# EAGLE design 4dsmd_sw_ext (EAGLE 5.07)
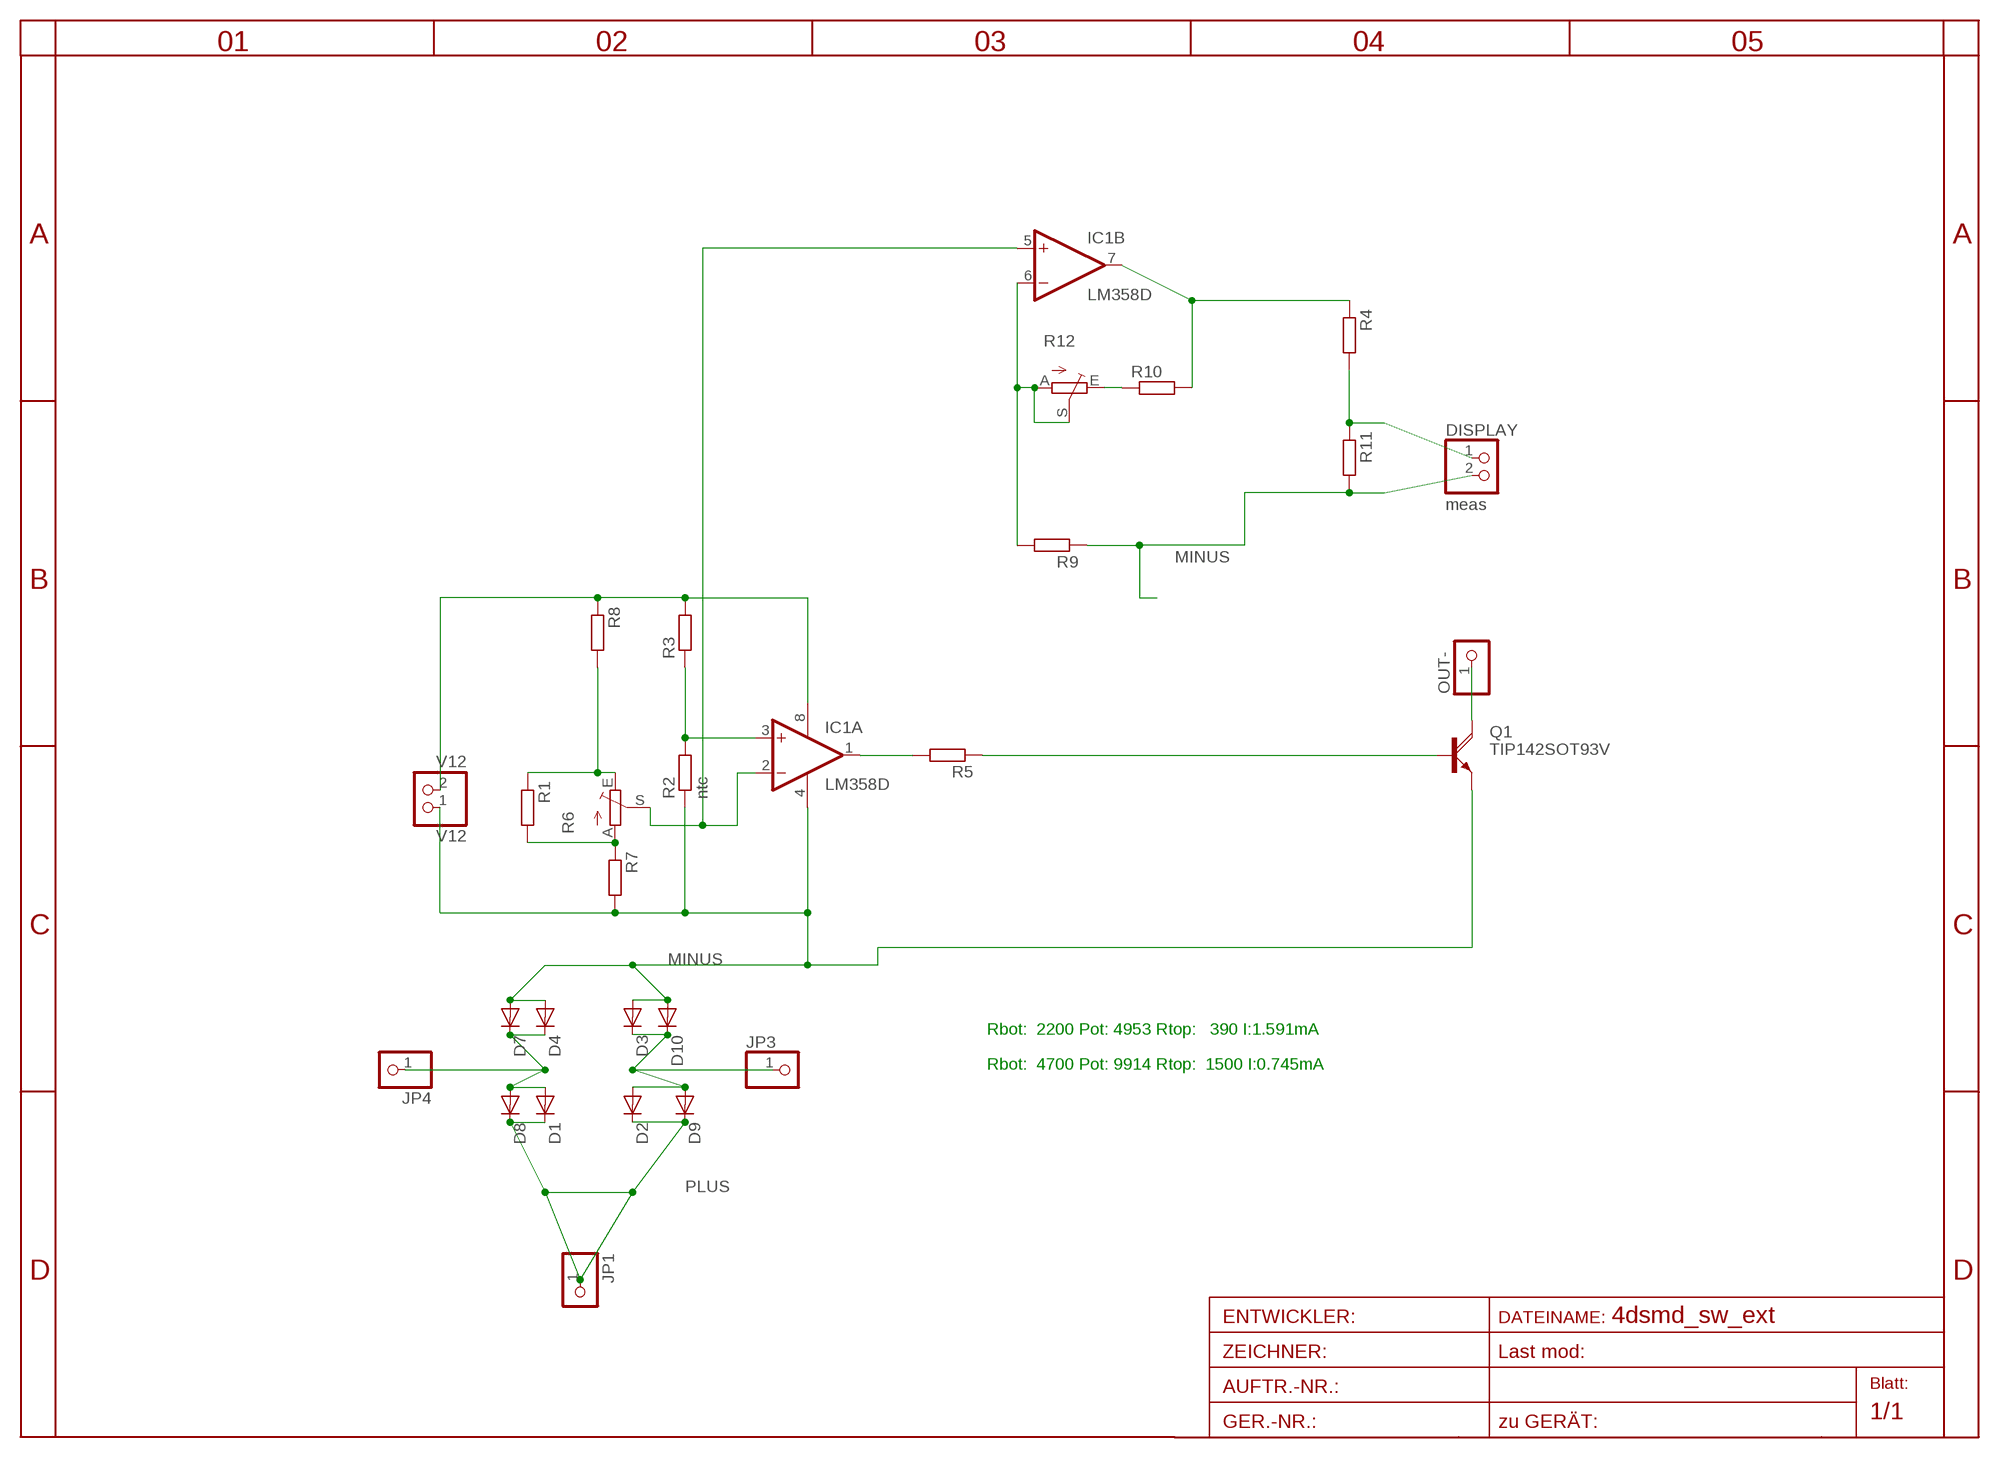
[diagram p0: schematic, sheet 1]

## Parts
D1  DIODE-SMC  [SMC]
D2  DIODE-SMC  [SMC]
D3  DIODE-SMC  [SMC]
D4  DIODE-SMC  [SMC]
D7  DIODE-SMC  [SMC]
D8  DIODE-SMC  [SMC]
D9  DIODE-SMC  [SMC]
D10  DIODE-SMC  [SMC]
DISPLAY  meas  PINHD-1X2STR  [1X02]
IC1  LM358D  [SO08]
JP1  PINHD-1X12MM2  [1X2MM2]
JP3  PINHD-1X12MM2  [1X2MM2]
JP4  PINHD-1X12MM2  [1X2MM2]
OUT-  PINHD-1X12MM2  [1X2MM2]
Q1  TIP142SOT93V  [SOT93V]
R1  R-EU_R1206  [R1206]
R2  ntc  R-EU_0204/5  [0204/5]
R3  R-EU_R0805  [R0805]
R4  R-EU_R0805  [R0805]
R5  R-EU_0204/3  [0204/3]
R6  TRIM_EU-RAND160  [RANDL]
R7  R-EU_R1206  [R1206]
R8  R-EU_R1206  [R1206]
R9  R-EU_R0805  [R0805]
R10  R-EU_R0805  [R0805]
R11  R-EU_R0805  [R0805]
R12  TRIM_EU-CA6V  [CA6V]
V12  V12  PINHD-1X2STR  [1X02]

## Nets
A: R1.2 R6.A R7.1
AC1: D1.A D4.C D7.C D8.A JP4.1
AC2: D2.A D3.C D9.A D10.C JP3.1
E: R1.1 R6.E R8.2
KKK: IC1.6(B:-IN) R9.2 R12.A R12.S
MINUS: D3.A D4.A D7.A D10.A DISPLAY.2 IC1.4(P:V-) Q1.E R2.1 R7.2 R9.1 R11.2 V12.1
N$1: DISPLAY.1 R4.2 R11.1
N$2: IC1.2(A:-IN) IC1.5(B:+IN) R6.S
N$3: IC1.1(A:OUT) R5.2
N$4: R10.1 R12.E
N$5: IC1.3(A:+IN) R2.2 R3.1
N$6: Q1.B R5.1
N$8: OUT-.1 Q1.C
N$11: IC1.7(B:OUT) R4.1 R10.2
PLUS: D1.C D2.C D8.C D9.C JP1.1
S: IC1.8(P:V+) R3.2 R8.1 V12.2

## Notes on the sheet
- Rbot:  2200 Pot: 4953 Rtop:   390 I:1.591mA
- Rbot:  4700 Pot: 9914 Rtop:  1500 I:0.745mA

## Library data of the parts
D1-D4 D7-D10 = diode:DIODE-: DIODE
DISPLAY V12 = pinhead:PINHD-1X2: PIN HEADER
IC1 = linear:LM358: OP AMP also LM158; LM258; LM2904 Source: http://cache.national.com/ds/LM/LM158.pdf
JP1 JP3 JP4 OUT- = pinhead:PINHD-1X1: PIN HEADER
Q1 = transistor-power:TIP142: NPN DARLINGTON TRANSISTOR
R1-R5 R7-R11 = rcl:R-EU_: RESISTOR, European symbol
R6 R12 = pot:TRIM_EU-: POTENTIOMETER

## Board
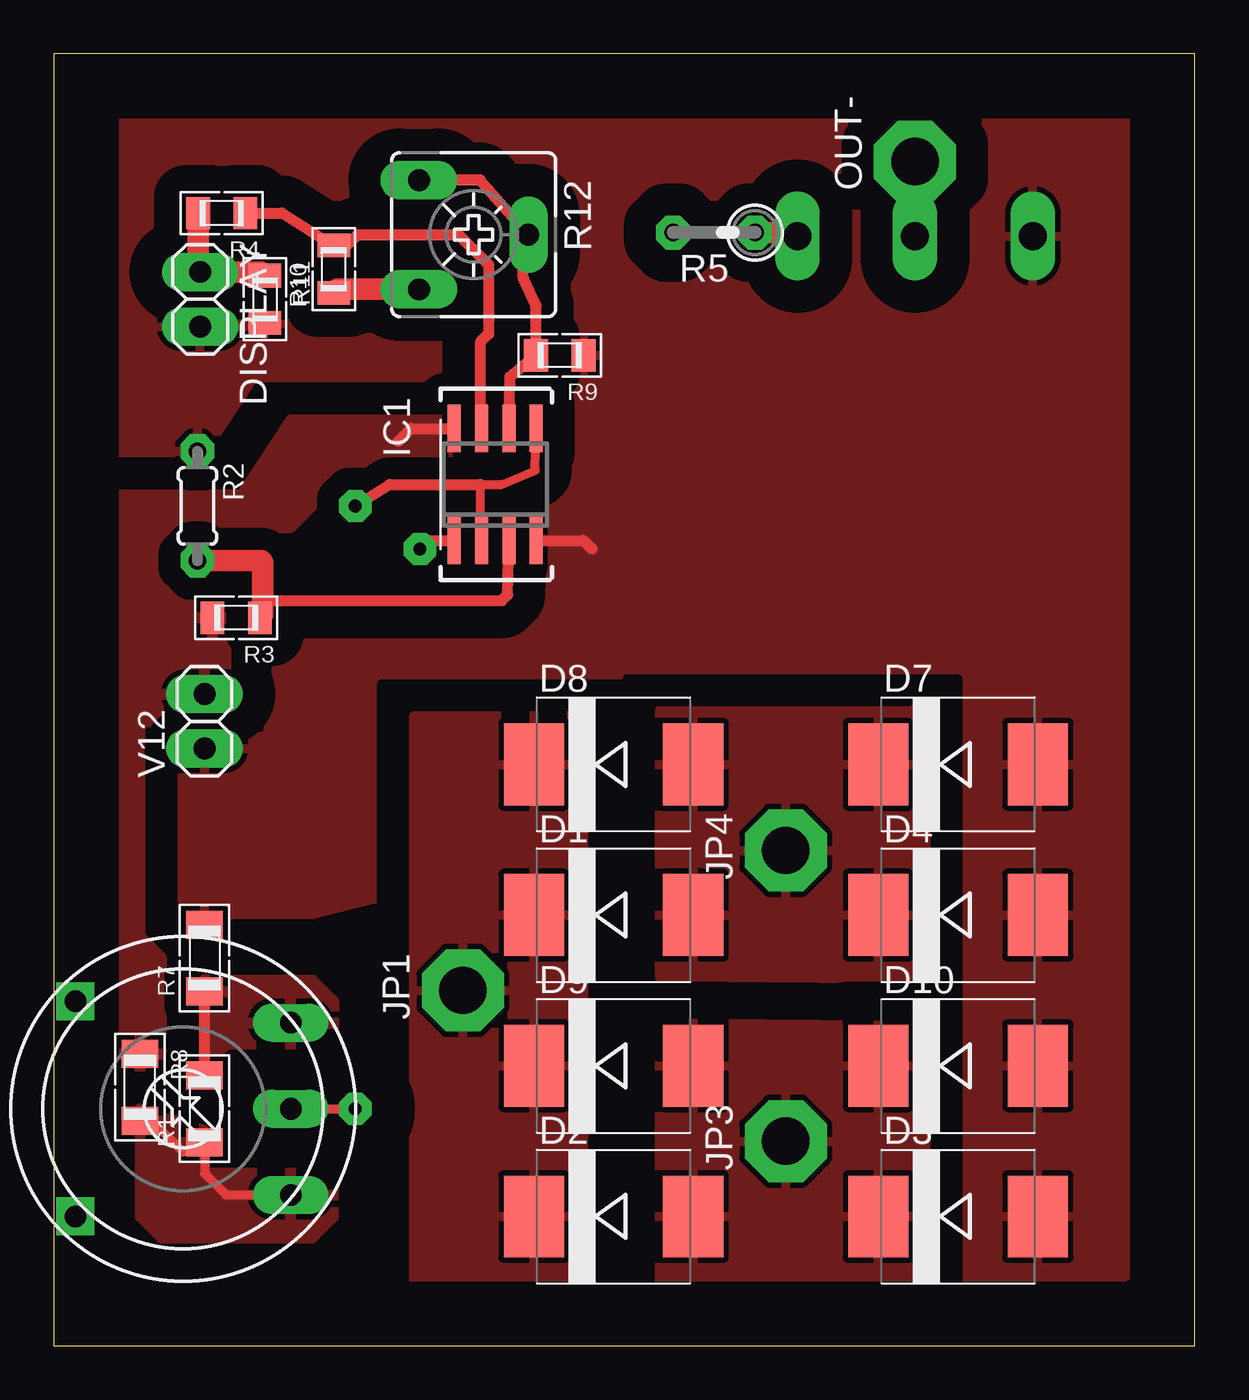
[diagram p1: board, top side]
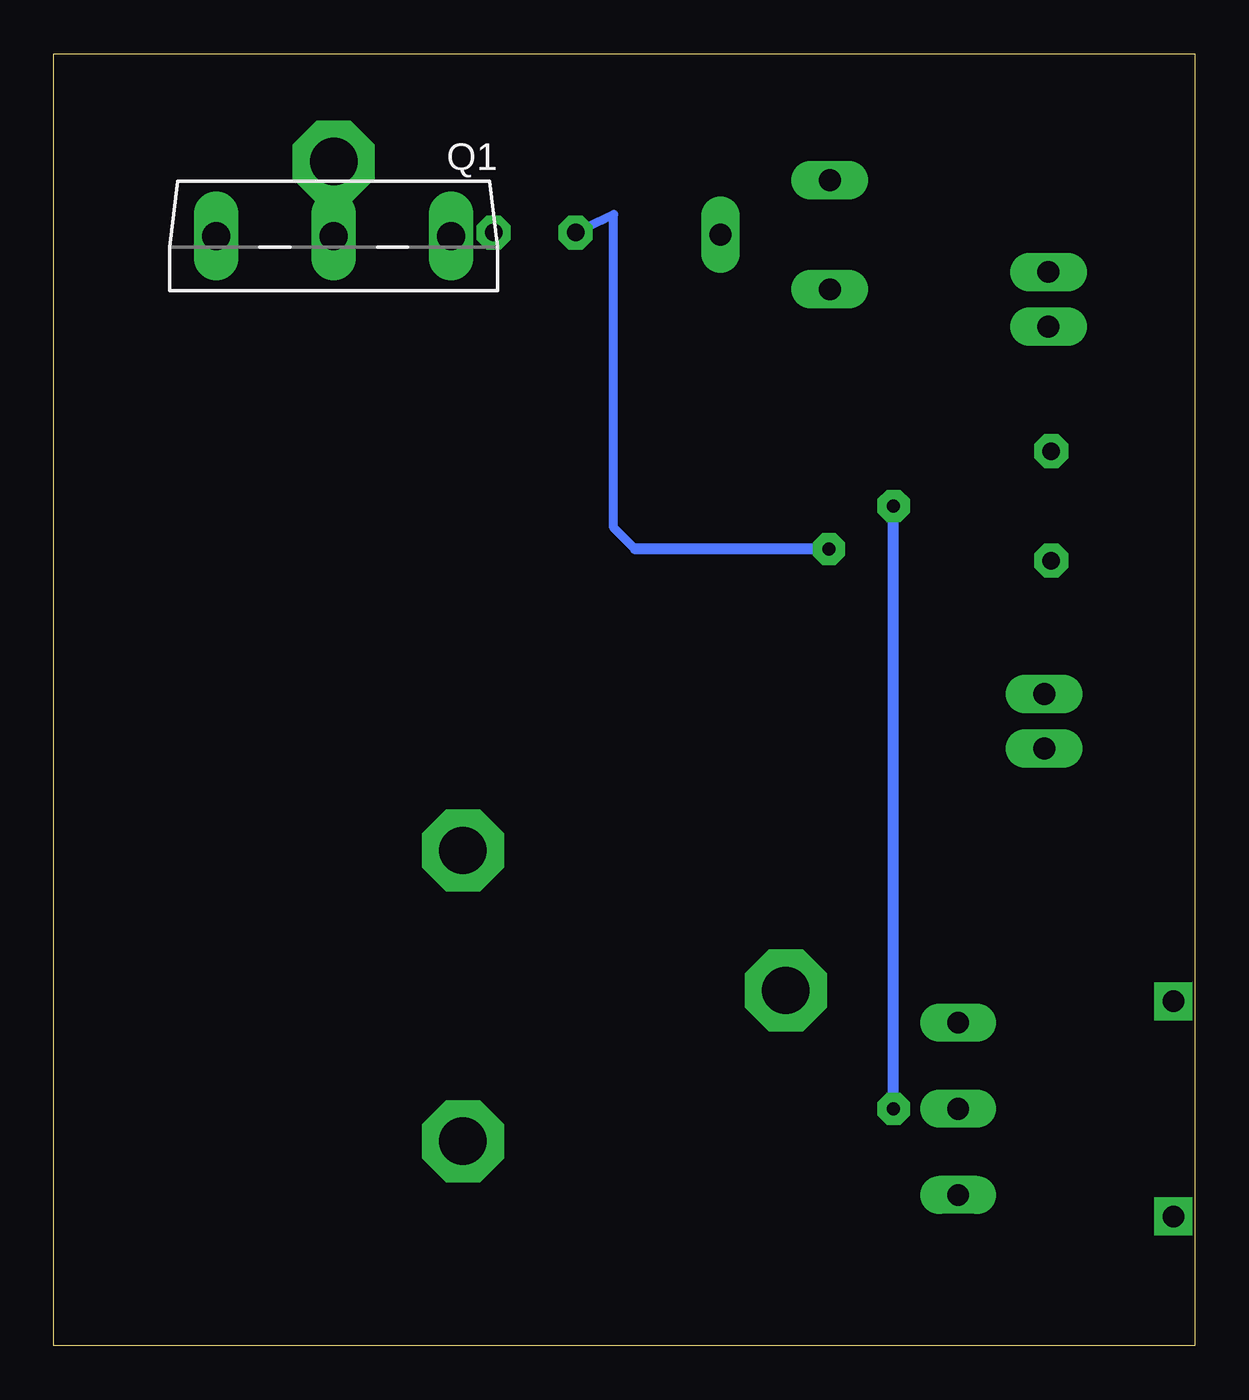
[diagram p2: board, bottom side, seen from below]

Size 53 x 60 mm. Coordinates in mm from the lower left corner, seen from the top.
Outline: 0,0 53,0 53,60 0,60 0,0
Copper layers (1*16): Top 0.035mm / dielectric 1.5mm / Bottom 0.035mm
Design rules "default *": minimum track width 10mil, minimum drill 20mil, track to track 8mil, track to pad 8mil, pad to pad 8mil, via to via 8mil, smd to smd 8mil, copper to edge 3mm, drill to drill 8mil, minimum pad ring 15mil, minimum via ring 8mil, stop-mask expansion 4mil, vias tented up to drill 0mil, thermal gap 10mil

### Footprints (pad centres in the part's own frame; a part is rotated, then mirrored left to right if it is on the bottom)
SMC = smd 2.8 x 3.8: A 3.7,0; C -3.7,0
1X02 = drill 1.016 pad 1.676 long: 1 -1.27,0; 2 1.27,0
SO08 = smd 0.6 x 2.2: 1 -1.905,-2.6; 2 -0.635,-2.6; 3 0.635,-2.6; 4 1.905,-2.6; 5 1.905,2.6; 6 0.635,2.6; 7 -0.635,2.6; 8 -1.905,2.6
1X2MM2 = drill 2.2 pad 3.81 octagon: 1 0,0
SOT93V = drill 1.3 pad 1.676 long: B -5.461,-2.54; C 0,-2.54; E 5.461,-2.54
R1206 = smd 1.3 x 1.7: 1 -1.55,0; 2 1.55,0
0204/5 = drill 0.813 octagon: 1 -2.54,0; 2 2.54,0
R0805 = smd 1.1 x 1.5: 1 -1.1,0; 2 1.1,0
0204/3 = drill 0.813 octagon: 1 -1.27,0; 2 2.54,0
RANDL = drill 1 long: A -4,5; E 4,5; S 0,5 | drill 1 square: P$1 -5,-5; P$2 5,-5
CA6V = drill 1.016 long: A -2.54,-2.54; E 2.54,-2.54; S 0,2.54

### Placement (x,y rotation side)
D1  26,20 0 top
D2  26,6 0 top
D3  42,6 0 top
D4  42,20 0 top
D7  42,27 0 top
D8  26,27 0 top
D9  26,13 0 top
D10  42,13 0 top
DISPLAY  6.8,48.6 270 top
IC1  20.5,40 0 top
JP1  19,16.5 90 top
JP3  34,9.5 90 top
JP4  34,23 90 top
OUT-  40,55 90 top
Q1  40,49 180 bottom
R1  7,11 90 top
R2  6.67,39 270 top
R3  8.47,33.81 180 top
R4  7.8,52.6 180 top
R5  31.3,51.7 180 top
R6  6,11 270 top
R7  7,18 90 top
R8  4,12 270 top
R9  23.5,46 180 top
R10  13,50 90 top
R11  9.8,48.6 270 top
R12  19.5,51.6 270 top
V12  7,29 90 top

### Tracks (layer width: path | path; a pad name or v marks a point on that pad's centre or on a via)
A
  Top 0.5: R1.2 R7.1
  pour Top (isolate 1): 7,17 12,17 13,16 13,14 8,14 7,13 7,16
AC1
  pour Top (isolate 2): 40.5,17 28.14,17.1 28.14,29.53 40.5,29.5
AC2
  pour Top (isolate 2.54): 28.14,2.86 28.14,15.02 40.5,14.9 40.5,2.9
E
  Top 0.406: R8.2 4.55,10.45 6,9 6.55,9 R1.1 7,8 8,7 R6.E
  pour Top (isolate 1): 4,11 4,6 5,5 12,5 13,6 13,8 7,8 7,10
KKK
  Top 0.406: 21.8,51.06 R12.S
  Top 0.5: IC1.6 21.18,44.98 R9.2 22.4,48.3 21.8,49.6 21.8,51.06 | R12.A 19.8,54.14 R12.S
MINUS
  Top 0.5: IC1.4 24.6,37.4 25,37
  pour Top (isolate 1.5, rank 2): 44.11,2.86 42,3 42,29.53 22,30 17,30 16,29 16,21 12,20 1,20 1,59 15,59 33,58 50,58 51.73,4.4 49.19,2.86
N$1
  Top 1: R4.2 6.7,49.97 DISPLAY.1 9.63,49.87 R11.1
N$2  (via drill 0.6 pad 1.5)
  Top 0.406: R6.S v14,11 | 19.8,37.06 IC1.2 19.8,37.09 19.8,40 20.8,40 22.36,40.66 IC1.5
  Top 0.5: v14,39 15.6,40 19.8,40
  Bottom 0.5: v14,11 v14,39
N$3  (via drill 0.6 pad 1.5)
  Top 0.406: v17,37 17.4,37.4
  Top 0.5: 17.4,37.4 IC1.1
  Bottom 0.406: 26,37 27,38 27,52.54 R5.2
  Bottom 0.5: v17,37 26,37
N$4
  Top 1: R12.E 13.16,49.06 R10.1
N$5
  Top 0.406: R3.1 9.82,34.6
  Top 0.5: IC1.3 21.09,34.88 20.8,34.6 9.82,34.6
  Top 1: R2.2 9.64,36.46 9.7,36.4 9.7,33.94 R3.1
N$6
  Top 1: R5.1 34.38,51.7 Q1.B
N$8
  Top 0.5: Q1.C OUT-.1
N$11
  Top 0.406: R10.2 13.6,51.1 | 19.8,42.3 IC1.7
  Top 0.5: R4.1 10.6,52.6 R10.2 | 13.6,51.1 14.1,51.6 18.8,51.6 20.2,50.2 20.2,47 19.8,46.6 19.8,42.3
PLUS
  pour Top (isolate 2): 16.71,2.86 16.71,29.26 24.6,29.26 24.6,2.86
S
  Top 0.5: IC1.8 16.6,42.6 16,42
  pour Top (isolate 1.016): 3,13 5,13 5,18 4,19 4,29 7,29 8,30 8,34 7,34 5,36 7,38 11,38 14,41 19,41 19,43 11,43 8.7,39.5 1.7,39.5 2,19 3,18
